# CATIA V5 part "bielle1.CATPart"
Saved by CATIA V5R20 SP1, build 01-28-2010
Part number: bielle1
Bounding box of the stored display mesh (mm): x 100 to 200, y -50 to 50, z -50 to 900
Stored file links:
  C:\Users\Nicolas\Documents\Ifma\2A\S3\iao\projet\bielle1.CATPart
  C:\Users\Nicolas\Documents\Ifma\2A\S3\iao\projet\Product1.CATProduct
  C:\Users\Nicolas\Documents\Ifma\2A\S3\iao\projet\Squelette.CATPart
  C:\Users\Nicolas\Documents\Ifma\2A\S3\iao\projet\bati.CATPart
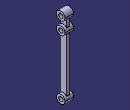
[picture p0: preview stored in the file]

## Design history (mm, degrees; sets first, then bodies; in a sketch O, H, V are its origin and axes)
Set1
  Plane1: linked copy from another document
  DatumPoint1: linked copy from another document
  Line1: linked copy from another document
  Line2: linked copy from another document
  Plane2: linked copy from another document
  Plane3: linked copy from another document
  Point1 to Point3: linked copy from another document
Body1 (main body)
  Sketch1 on Plane1, origin (150, 0, 0), H (0, 1, 0), V (0, 0, 1)
    arc A1 centre (0, 0) radius 50 from (-37.5, 33.0719) to (37.5, 33.0719) ccw
    point P1 (0, 0)
    arc A2 centre (0, 700) radius 50 from (37.5, 666.9281) to (37.5, 733.0719) ccw
    point P2 (0, 700)
    arc A3 centre (0, 850) radius 50 from (37.5, 816.9281) to (-37.5, 816.9281) ccw
    point P3 (0, 850)
    reference projected point E1 (0, 0) from vertex of DatumPoint1
    reference projected point E2 (0, 700) from Line1
    reference projected point E3 (0, 850) from Line2
    point P4 (-37.5, 33.0719)
    line L1 (37.5, 33.0719) -> (37.5, 666.9281)
    line L2 (-37.5, 816.9281) -> (-37.5, 733.0719)
    point P5 (37.5, 33.0719)
    point P8 (-37.5, 666.9281)
    point P10 (37.5, 733.0719)
    arc A4 centre (0, 700) radius 50 from (-37.5, 733.0719) to (-37.5, 666.9281) ccw
    line L3 (37.5, 733.0719) -> (37.5, 816.9281)
    line L4 (-37.5, 666.9281) -> (-37.5, 33.0719)
    construction line L5 (-37.5, 33.0719) -> (37.5, 33.0719)
    point P12 (-37.5, 33.0719)
    point P13 (37.5, 33.0719)
    radius A3 = 50
    radius A2 = 50
    radius A1 = 50
    distance L1 L2 = 75
    coincidence: P1 E1, P2 E2, P3 E3, L2 P8, L1 P10, A2 A4, L1 L3, L2 L4, P12 A1, P13 A1, L5 P5, P4 P12
    vertical: L1 V, L2 V, L3 V, L4 V
    parallelism: L4 L1
    horizontal: L5 H
  Pad1: profile Sketch1, direction (1, 0, 0), length 20, mirrored extent
  Sketch2 on Plane1, origin (150, 0, 0), H (0, 1, 0), V (0, 0, 1)
    circle A1 centre (0, 0) radius 50
    circle A2 centre (0, 700) radius 50
    circle A3 centre (0, 850) radius 50
    reference projected arc E1 centre (0, 700) radius 50 from (37.5, 666.9281) to (37.5, 733.0719) ccw from edge [face of Pad1 from Sketch1.A2 | end face of Pad1]
    reference projected arc E2 centre (0, 850) radius 50 from (37.5, 816.9281) to (-37.5, 816.9281) ccw from edge [face of Pad1 from Sketch1.A3 | end face of Pad1]
    reference projected arc E3 centre (0, 0) radius 50 from (-37.5, 33.0719) to (37.5, 33.0719) ccw from edge [face of Pad1 from Sketch1.A1 | end face of Pad1]
    coincidence: A2 E1, A3 E2, A1 E3
  Pad2: profile Sketch2, direction (1, 0, 0), up to Plane2, opposite side up to Plane3
  Sketch3 on start face of Pad2, origin (200, 0, 700), H (0, 1, 0), V (0, 0, 1)
    point P1 (0, 0)
    reference projected point E1 (0, 0) from Point1
    coincidence: E1 P1
  Hole1: placed by Sketch3, at (200, 0, 700) direction (-1, 0, 0), diameter 50, through (limit type 3)
  Sketch4 on start face of Pad2, origin (200, 0, 850), H (0, 1, 0), V (0, 0, 1)
    point P1 (0, 0)
    reference projected point E1 (0, 0) from Point2
    coincidence: E1 P1
  Hole2: placed by Sketch4, at (200, 0, 850) direction (-1, 0, 0), diameter 50, through (limit type 3)
  Sketch5 on start face of Pad2, origin (200, 0, 0), H (0, 1, 0), V (0, 0, 1)
    point P1 (0, 0)
    reference projected point E1 (0, 0) from Point3
    coincidence: E1 P1
  Hole3: placed by Sketch5, at (200, 0, 0) direction (-1, 0, 0), diameter 50, through (limit type 3)
  Fillet1: radius 5, on edge [face of Pad2 from Sketch2.A1 | face of Pad1 from Sketch1.L4]; edge [face of Pad1 from Sketch1.L1 | face of Pad2 from Sketch2.A1]; edge [face of Pad1 from Sketch1.L4 | face of Pad2]; edge [face of Pad2 | face of Pad1 from Sketch1.L2]; edge [face of Pad1 from Sketch1.L2 | face of Pad2 from Sketch2.A3]; edge [face of Pad2 from Sketch2.A3 | face of Pad1 from Sketch1.L3]; edge [face of Pad1 from Sketch1.L3 | face of Pad2]; edge [face of Pad2 | face of Pad1 from Sketch1.L1]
